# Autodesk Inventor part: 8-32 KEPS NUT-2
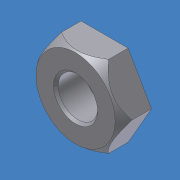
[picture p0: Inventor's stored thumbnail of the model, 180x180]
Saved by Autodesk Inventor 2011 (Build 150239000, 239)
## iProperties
Created: 2007-09
Part Number: 8-32 KEPS NUT-2
Document SubType Name: Modeling
Material: Stainless Steel
Density: 8.08 g/cm^3
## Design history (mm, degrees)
feature "Base1"
body "Solid1"
